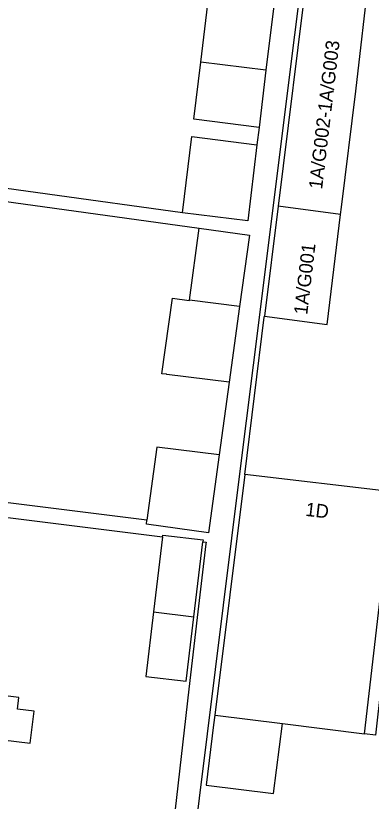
# Model space of a CAD drawing. Extents: x 161696 to 162377, y 380761 to 381673.
# Drawn here: x 162247.3 to 162273.5, y 381258.9 to 381316.7 of the extents above; entities that cross this region are included whole.
import ezdxf

# ---------------------------------------------------------------- set-up
doc = ezdxf.new("R2010")
doc.units = 0
for name, color, linetype in [('IMGEO_Pand', 7, 'Continuous'), ('IMGEO_Pand_nummerreeks', 7, 'Continuous'), ('IMGEO_Voetpad_open', 7, 'Continuous')]:
    doc.layers.add(name, color=color, linetype=linetype)

msp = doc.modelspace()

# ---------------------------------------------------------------- linework, layer by layer
at = {"layer": 'IMGEO_Pand'}
for points in [[(162268.799, 381320.541), (162268.777, 381320.363), (162266.582, 381302.726)], [(162271.178, 381302.121), (162271.243, 381302.657), (162272.323, 381311.201), (162273.325, 381319.949), (162272.813, 381320.011)], [(162260.895, 381313.321), (162261.495, 381318.25), (162266.294, 381317.666)], [(162266.294, 381317.666), (162265.692, 381312.724)], [(162265.182, 381308.528), (162260.386, 381309.134), (162260.895, 381313.321)], [(162265.692, 381312.724), (162260.895, 381313.321)], [(162265.692, 381312.724), (162265.182, 381308.528)], [(162259.547, 381302.233), (162260.23, 381307.853), (162265.026, 381307.247)], [(162265.026, 381307.247), (162264.345, 381301.648), (162259.547, 381302.233)], [(162266.582, 381302.726), (162265.577, 381294.639)], [(162271.178, 381302.121), (162266.582, 381302.726)], [(162265.577, 381294.639), (162270.197, 381294.026), (162271.178, 381302.121)], [(162260.049, 381295.804), (162260.78, 381301.109)], [(162260.78, 381301.109), (162264.468, 381300.601), (162263.744, 381295.344)], [(162262.977, 381289.783), (162258.401, 381290.352), (162258.366, 381290.357), (162258.03, 381290.403), (162258.796, 381295.961), (162260.047, 381295.789), (162260.049, 381295.804)], [(162263.744, 381295.344), (162260.049, 381295.804)], [(162263.744, 381295.344), (162262.977, 381289.783)], [(162262.24, 381284.436), (162257.664, 381285.005), (162256.921, 381279.617)], [(162262.24, 381284.436), (162261.45, 381278.705), (162256.882, 381279.334), (162256.921, 381279.617)], [(162264.127, 381282.983), (162261.924, 381265.275)], [(162272.937, 381263.902), (162275.022, 381281.707), (162264.127, 381282.983)], [(162258.074, 381278.401), (162258.09, 381278.534), (162261.064, 381278.185), (162261.045, 381278.03)], [(162258.074, 381278.401), (162257.413, 381272.875)], [(162260.385, 381272.505), (162261.045, 381278.03)], [(162257.413, 381272.875), (162256.844, 381268.118), (162259.818, 381267.768), (162260.385, 381272.505)], [(162257.413, 381272.875), (162260.385, 381272.505)], [(162244.087, 381263.741), (162248.316, 381263.214), (162248.61, 381265.578), (162247.385, 381265.731), (162247.491, 381266.583), (162237.188, 381267.865), (162237.127, 381267.372)], [(162261.924, 381265.275), (162261.835, 381264.56), (162261.283, 381260.124), (162266.258, 381259.504), (162266.9, 381264.655)], [(162261.924, 381265.275), (162261.954, 381265.271), (162266.9, 381264.655)], [(162266.9, 381264.655), (162272.937, 381263.902)]]:
    msp.add_lwpolyline(points, dxfattribs=at)
at = {"layer": 'IMGEO_Voetpad_open'}
for points in [[(162248.568, 381250.77), (162259.583, 381249.511), (162263.772, 381283.024), (162265.259, 381294.924), (162266.831, 381307.5), (162271.787, 381347.044)], [(162265.182, 381308.528), (162265.026, 381307.247)], [(162259.547, 381302.233), (162239.631, 381304.981)], [(162241.734, 381303.732), (162260.78, 381301.109)], [(162264.127, 381282.983), (162265.567, 381294.564), (162265.577, 381294.639)], [(162262.977, 381289.783), (162262.24, 381284.436)], [(162256.921, 381279.617), (162233.496, 381282.545)], [(162285.126, 381280.551), (162276.006, 381281.597), (162275.829, 381281.619), (162275.223, 381276.269), (162275.063, 381274.948), (162274.601, 381271.253), (162273.75, 381263.809), (162272.937, 381263.902)], [(162236.647, 381281.081), (162258.074, 381278.401)], [(162261.045, 381278.03), (162261.283, 381278), (162261.27, 381277.887), (162260.634, 381272.474), (162260.014, 381267.198), (162258.536, 381254.262), (162258.295, 381252.155), (162258.183, 381251.173), (162235.405, 381253.776)]]:
    msp.add_lwpolyline(points, dxfattribs=at)

# ---------------------------------------------------------------- texts
at = {"layer": 'IMGEO_Pand_nummerreeks'}
for s, rotation, p in [('1A/G002-1A/G003', 83.21639, (162269.825, 381303.94)), ('1A/G001', 83.21639, (162268.727, 381294.702)), ('1D', 353.31931, (162268.563, 381279.946))]:
    msp.add_text(s, height=1, rotation=rotation, dxfattribs=at).set_placement(p)

doc.saveas('drawing.dxf')
